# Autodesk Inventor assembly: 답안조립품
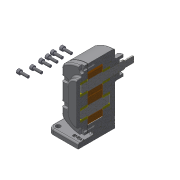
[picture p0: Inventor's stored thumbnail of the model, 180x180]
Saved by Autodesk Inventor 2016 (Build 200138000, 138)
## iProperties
Created: 2019-03
Part Number: 답안조립품
Document SubType Name: Assembly
Designer: 2-PC11
Author: 2-PC11
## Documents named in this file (10)
- C:\Users\2-PC11\Desktop\490308V1001\답안조립품.iam
- C:\Users\2-PC11\Desktop\490308V1001\본체.ipt
- C:\Users\2-PC11\Desktop\490308V1001\메인축.ipt
- C:\Users\2-PC11\Desktop\490308V1001\서브축.ipt
- C:\Users\2-PC11\Desktop\490308V1001\키 6 x 6 x 18.ipt
- C:\Users\2-PC11\Desktop\490308V1001\스퍼기어.ipt
- C:\Users\2-PC11\Desktop\490308V1001\베어링부시.ipt
- C:\Users\2-PC11\Desktop\490308V1001\개스킷.ipt
- C:\Users\2-PC11\Desktop\490308V1001\커버.ipt
- C:\Users\2-PC11\Desktop\490308V1001\볼트 M5.ipt
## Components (1 placed, 1 different names)
1. 개스킷:1
